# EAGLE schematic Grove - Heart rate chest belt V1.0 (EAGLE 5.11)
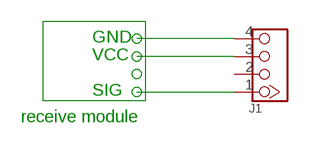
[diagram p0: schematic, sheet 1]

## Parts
J1  TWIG-4P-2.0-2.0  [4P-2.0]

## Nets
N$2: J1.4
N$3: J1.3
N$6: J1.1
Unconnected: J1.2

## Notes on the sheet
- GND
- VCC
- SIG
- receive module

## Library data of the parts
J1 = Connector:TWIG-4P-2.0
